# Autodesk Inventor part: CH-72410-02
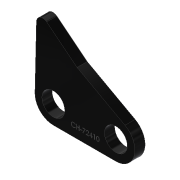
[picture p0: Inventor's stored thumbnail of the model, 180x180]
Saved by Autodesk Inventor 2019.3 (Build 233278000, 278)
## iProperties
Created: 2012-10
Part Number: CH-72410-02
Material: Ogólny
Document SubType Name: Modeling
Designer: CADENGINEERING4
Density: 1 g/cm^3
Appearance: Gładki — czarny
Author: CADENGINEERING4
Revision Number: ÈÎºÎ
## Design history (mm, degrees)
feature "ÇÐ³ý-À­Éì1"
node "Bryła1"
